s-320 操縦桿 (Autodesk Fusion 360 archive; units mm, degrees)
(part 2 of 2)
sketch "スケッチ34" plane through (0, -17.75, 0) normal (0, -1, 0) x axis (1, 0, 0)
  line L1 (26.4851, 42.5538) -> (46.528, 114.8261)
  line L2 (24.2607, 0.3616) -> (26.4851, 42.5538)
  line L3 (40.9088, -4.9758) -> (34.0399, -5.6547)
  line L4 (39.7489, 5.0904) -> (40.9088, 4.9758)
  line L5 (55.394, 34.5366) -> (39.7489, 5.0904)
  line L6 (75.4369, 106.8089) -> (55.394, 34.5366)
  line L7 (46.528, 114.8261) -> (75.4369, 106.8089)
  line L8 (69.2825, 103.327) -> (50.0099, 108.6717)
  line L9 (51.912, 40.691) -> (69.2825, 103.327)
  line L10 (32.6394, 46.0358) -> (51.912, 40.691)
  line L11 (50.0099, 108.6717) -> (32.6394, 46.0358)
  line L12 (26.4851, 42.5538) -> (55.394, 34.5366)
  line L13 (46.528, 114.8261) -> (26.4851, 42.5538)
  line L14 (30.25, 0) -> (60.9824, 110.8175)
  line L15 (30.8401, 5.9709) -> (40.9088, 4.9758)
  curve K1 (39.7489, 5.0904) -> (55.394, 34.5366)
  curve K2 (55.9608, 15.3561) -> (39.182, 24.2709)
  line L16 (56.7302, 39.3548) -> (47.2453, 33.4232)
  line L17 (34.0399, -5.6547) -> (28.0686, -16.8936)
  line L18 (19.6561, -9.6776) -> (19.6234, -9.6584)
  circle C1 centre (30.25, 0) radius 3.25
  circle C2 centre (40.417, 0) radius 2
  arc A1 centre (40.417, 0) radius 5 clockwise from (40.9088, 4.9758) to (40.9088, -4.9758)
  circle C3 centre (69.2825, 103.327) radius 2.75
  circle C4 centre (50.0099, 108.6717) radius 2.75
  circle C5 centre (32.6394, 46.0358) radius 2.75
  circle C6 centre (50.0099, 108.6717) radius 1.35
  circle C7 centre (69.2825, 103.327) radius 1.35
  circle C8 centre (32.6394, 46.0358) radius 1.35
  closed curve K3 centre (47.5714, 19.8135)
  arc A2 centre (8.7979, 1.4348) radius 15.5 clockwise from (24.2607, 0.3616) to (19.6234, -9.6584)
  arc A3 centre (23.0532, -14.2288) radius 5.6793 clockwise from (28.0686, -16.8936) to (19.6561, -9.6776)
  circle C9 centre (51.912, 40.691) radius 1.35
  circle C10 centre (51.912, 40.691) radius 2.75
  point P16 (50.0099, 108.6717)
  point P19 (50.0099, 108.6717)
  point P18 (32.6394, 46.0358)
  point P17 (69.2825, 103.327)
  point P11 (55.394, 34.5366)
  point P23 (55.394, 34.5366)
  point P5 (26.4851, 42.5538)
  point P24 (26.4851, 42.5538)
  point P13 (69.2825, 103.327)
  point P20 (69.2825, 103.327)
  point P15 (32.6394, 46.0358)
  point P22 (32.6394, 46.0358)
  point P34 (55.394, 34.5366)
  point P35 (39.7489, 5.0904)
  point P36 (39.182, 24.2709)
  point P37 (55.9608, 15.3561)
  point P27 (39.7489, 5.0904)
  point P38 (47.2453, 33.4232)
  point P39 (56.7302, 39.3548)
  point P21 (51.912, 40.691)
  point P46 (51.912, 40.691)
  point P14 (50.0099, 108.6717)
  equal C3 C4
  equal C4 C5
  concentric C4 C6
  concentric C3 C7
  concentric C5 C8
  equal C6 C7
  coincident P16 P19
  coincident P18 L10
  coincident P17 L9
  coincident P11 P23
  coincident P5 P24
  coincident P13 P20
  coincident P15 P22
  parallel L11 L13
  perpendicular L10 L11
  equal C6 C8
  coincident K3 P34
  coincident K3 P35
  coincident K3 P36
  coincident K3 P37
  parallel L5 K1
  coincident P23 K3
  coincident P23 P34
  coincident P27 P35
  coincident K3 P38
  coincident L6 P39
  tangent K3 L16
  coincident P21 P46
  concentric C9 C10
  equal C8 C9
  equal C5 C10
  dimension "d449" diameter C4 = 5.5
  dimension "d450" diameter C6 = 2.7
  dimension "d452" distance L7 L8 = 5
  dimension "d454" distance L6 L9 = 5
  dimension "d463" distance P14 L13 = 5
  dimension "d648" distance L10 L12 = 5
  dimension "d653" = 19
  dimension "d654" distance P23 P39 = 5
extrude "押し出し121" cut sketch "スケッチ34" profile of L5 L6 K3 L16 to an object
extrude "押し出し96" cut sketch "スケッチ34" profile of C3 C4 C5 C6 C7 C8 C9 C10 against normal blind 0.7
extrude "押し出し97" cut sketch "スケッチ34" profile of C6 C7 C8 C9 against normal blind 20
work_plane "作業平面6" AlongDistance 2
sketch "スケッチ35" plane through (-70, 0, 0) normal (-1, 0, 0) x axis (0, -1, 0)
  line L1 (11.625, 20.1351) -> (0, 0)
  line L2 (-11.625, 20.1351) -> (0, 0)
  line L3 (0, 23.25) -> (0, 0)
  circle C1 centre (0, 0) radius 23.25
  circle C2 centre (0, 0) radius 23.25
  point P1 (0, 0)
  point P2 (0, 0)
  point P4 (0, 0)
  point P6 (0, 0)
  point P5 (-11.625, 20.1351)
  point P3 (11.625, 20.1351)
  point P7 (0, 0)
  point P8 (0, 23.25)
  coincident P1 P2
  coincident P1 P4
  coincident P1 P6
  coincident P5 C1
  coincident P3 C1
  coincident P6 P7
  coincident C1 P8
  vertical L3
  symmetric L1 L2 L3
  equal C1 C2
  dimension "d472" angle L1 L2 = 60
extrude "押し出し99" cut sketch "スケッチ35" profile of L1 L2 C1 C2 along normal blind 6
sketch "スケッチ36" plane through (0, 0, 0) normal (0, 0, 1) x axis (1, 0, 0)
  line L1 (-70, 7.875) -> (-70, -7.875)
  line L2 (-97.5, 0) -> (0, 0)
  circle C1 centre (-73, 0) radius 3
  point P1 (0, 0)
  point P5 (0, 0)
  point P6 (-97.5, 0)
  point P7 (-97.5, 0)
  point P2 (-73, 0)
  tangent C1 L1
  coincident P1 P5
  horizontal L2
  coincident P6 P7
  coincident P2 L2
  dimension "d475" diameter C1 = 6
extrude "押し出し100" cut sketch "スケッチ36" profile of C1 no distance stored
work_plane "作業平面7" RotateAngle -30
sketch "スケッチ37" plane through (0, -7.875, 13.6399) normal (0, -0.5, 0.866) x axis (0, -0.866, -0.5)
  line L1 (0, -76) -> (0, -70)
  circle C1 centre (0, -73) radius 3
  point P3 (0, -76)
  point P4 (0, -70)
  point P2 (0, -73)
  coincident C1 P3
  coincident C1 P4
  coincident P2 L1
work_plane "作業平面8" RotateAngle 30
sketch "スケッチ38" plane through (0, 7.875, 13.6399) normal (0, 0.5, 0.866) x axis (0, -0.866, 0.5)
  line L1 (0, -70) -> (0, -76)
  circle C1 centre (0, -73) radius 3
  point P3 (0, -76)
  point P4 (0, -70)
  point P2 (0, -73)
  coincident C1 P3
  coincident C1 P4
  coincident P2 L1
extrude "押し出し101" cut sketch "スケッチ38" against normal blind 5
extrude "押し出し102" cut sketch "スケッチ37" against normal blind 5
work_plane "作業平面9" RotateAngle -90
extrude "押し出し103" new body sketch "スケッチ36" profile of C1 blind 13.5 from offset 10
sketch "スケッチ40" plane through (0, 0, 23.5) normal (0, 0, 1) x axis (-1, 0, 0)
  circle C1 centre (73, 0) radius 3
  circle C2 centre (73, 0) radius 4.5
  concentric C1 C2
  dimension "d489" diameter C2 = 9
extrude "押し出し104" add sketch "スケッチ40" along normal blind 1.5
sketch "スケッチ41" plane through (8, 0, 0) normal (1, 0, 0) x axis (0, 1, 0)
  line L1 (-19.1147, -8.074) -> (-32.7694, 24.2525)
  line L2 (14.5382, -14.5382) -> (14.9765, -14.9765)
  line L3 (1.3727, -15.6901) -> (14.5382, -14.5382)
  line L4 (-14.5382, 14.5382) -> (-15.6901, 1.3727)
  line L5 (-22.1855, 22.1855) -> (-14.5382, 14.5382)
  line L6 (3.2527, -35.7796) -> (-15.7847, -13.4687)
  line L7 (28.8089, -61.3359) -> (3.2527, -35.7796)
  line L8 (13.8593, -32.2441) -> (35.88, -54.2648)
  line L9 (18.1019, -20.9304) -> (13.8593, -25.173)
  line L10 (14.9765, -17.8049) -> (18.1019, -20.9304)
  arc A1 centre (-26.7817, 26.7817) radius 6.5 clockwise from (-32.7694, 24.2525) to (-22.1855, 22.1855)
  arc A2 centre (0, 0) radius 20.75 clockwise from (-15.7847, -13.4687) to (-19.1147, -8.074)
  arc A3 centre (0, 0) radius 15.75 clockwise from (1.3727, -15.6901) to (-15.6901, 1.3727)
  circle C1 centre (-26.7817, 26.7817) radius 2
  circle C2 centre (-26.7817, 26.7817) radius 2
  circle C3 centre (32.3445, -57.8003) radius 2
  arc A4 centre (32.3445, -57.8003) radius 5 clockwise from (35.88, -54.2648) to (28.8089, -61.3359)
  arc A5 centre (17.3948, -28.7085) radius 5 clockwise from (13.8593, -32.2441) to (13.8593, -25.173)
  arc A6 centre (16.3907, -16.3907) radius 2 clockwise from (14.9765, -17.8049) to (14.9765, -14.9765)
sketch "スケッチ42" plane through (0, 0, 0) normal (-1, 0, 0) x axis (0, -1, 0)
  line L1 (-8.0798, 13.5196) -> (23.4471, 32.3612)
  line L2 (32.3612, 23.4472) -> (13.5196, -8.0798)
  arc A1 centre (0, 0) radius 15.75 clockwise from (-8.0798, 13.5196) to (13.5196, -8.0798)
  arc A2 centre (26.7817, 26.7817) radius 6.5 clockwise from (23.4471, 32.3612) to (32.3612, 23.4472)
  circle C1 centre (26.7817, 26.7817) radius 3.25
  circle C2 centre (26.7817, 26.7817) radius 3.5
  concentric C1 C2
  dimension "d615" diameter C1 = 6.5
extrude "押し出し117" new body sketch "スケッチ42" profile of C1 along normal blind 1.6
extrude "押し出し118" add sketch "スケッチ5" profile of C1 to an object second side blind -12
sketch "スケッチ43" plane through (0, 20.8728, 0) normal (0, 1, 0) x axis (-1, 0, 0)
  line L1 (-27.6519, -1.5) -> (-32.8481, -1.5)
  arc A1 centre (-30.25, 0) radius 3 clockwise from (-32.8481, -1.5) to (-27.6519, -1.5)
component_from_bodies "ボディ -> コンポーネント33"
component_from_bodies "ボディ -> コンポーネント34"
component_from_bodies "ボディ -> コンポーネント35"
component_from_bodies "ボディ -> コンポーネント36"
component_from_bodies "ボディ -> コンポーネント37"
component_from_bodies "ボディ -> コンポーネント38"
component_from_bodies "ボディ -> コンポーネント39"
component_from_bodies "ボディ -> コンポーネント40"
component_from_bodies "ボディ -> コンポーネント41"
component_from_bodies "ボディ -> コンポーネント42"
component_from_bodies "ボディ -> コンポーネント43"
component_from_bodies "ボディ -> コンポーネント44"
component_from_bodies "ボディ -> コンポーネント45"
component_from_bodies "ボディ -> コンポーネント46"
component_from_bodies "ボディ -> コンポーネント47"
component_from_bodies "ボディ -> コンポーネント48"
component_from_bodies "ボディ -> コンポーネント49"
component_from_bodies "ボディ -> コンポーネント50"
component_from_bodies "ボディ -> コンポーネント51"
component_from_bodies "ボディ -> コンポーネント52"
component_from_bodies "ボディ -> コンポーネント53"
component_from_bodies "ボディ -> コンポーネント54"
component_from_bodies "ボディ -> コンポーネント55"
component_from_bodies "ボディ -> コンポーネント56"
component_from_bodies "ボディ -> コンポーネント57"
component_from_bodies "ボディ -> コンポーネント58"
component_from_bodies "ボディ -> コンポーネント59"
component_from_bodies "ボディ -> コンポーネント60"
component_from_bodies "ボディ -> コンポーネント61"
component_from_bodies "ボディ -> コンポーネント62"
component_from_bodies "ボディ -> コンポーネント63"
component_from_bodies "ボディ -> コンポーネント64"
component_from_bodies "ボディ -> コンポーネント65"
component_from_bodies "ボディ -> コンポーネント66"
component_from_bodies "ボディ -> コンポーネント67"
component_from_bodies "ボディ -> コンポーネント68"
component_from_bodies "ボディ -> コンポーネント69"
fillet "フィレット1" radius 2.5
fillet "フィレット1" radius 2.5
fillet "フィレット2" radius 2.5
work_plane "作業平面10"
base_feature "基準フィーチャ1"
position "位置8"
sketch "スケッチ54" plane through (0, 0, 0) normal (0, 1, 0) x axis (1, 0, 0)
copy_paste "コピーと貼り付け1"
base_feature "基準フィーチャ1"
position "位置11"
copy_paste "コピーと貼り付け4"
copy_paste "コピーと貼り付け5"
copy_paste "コピーと貼り付け6"
base_feature "基準フィーチャ1"
base_feature "基準フィーチャ1"
remove_instance "RemoveInstance1"
position "位置10"
base_feature "基準フィーチャ1"
base_feature "基準フィーチャ1"
remove_instance "RemoveInstance2"
position "位置12"
base_feature "基準フィーチャ1"
base_feature "基準フィーチャ1"
position "位置13"
remove_instance "RemoveInstance3"
base_feature "基準フィーチャ1"
position "位置14"
remove_instance "RemoveInstance4"
base_feature "基準フィーチャ1"
position "位置15"
sketch "スケッチ55" plane through (0, -15.75, 0) normal (0, 1, 0) x axis (-1, 0, 0)
  line L1 (-56.7302, 39.3548) -> (-74.7688, 104.3999)
  line L2 (-47.2453, 33.4232) -> (-56.7302, 39.3548)
  line L3 (-40.9088, 4.9758) -> (-39.7489, 5.0904)
  line L4 (-34.0399, -5.6547) -> (-40.9088, -4.9758)
  line L5 (-28.0686, -16.8936) -> (-34.0399, -5.6547)
  line L6 (-19.6234, -9.6584) -> (-19.6561, -9.6776)
  line L7 (-26.4851, 42.5538) -> (-24.2607, 0.3616)
  line L8 (-45.8599, 112.417) -> (-26.4851, 42.5538)
  line L9 (-73.0278, 107.477) -> (-48.937, 114.158)
  line L10 (-37.167, 0) -> (-45.417, 0)
  line L11 (-37.167, 0) -> (-39.7489, 5.0904)
  line L12 (-39.7489, -5.0904) -> (-37.167, 0)
  arc A1 centre (-72.3597, 105.0679) radius 2.5 clockwise from (-74.7688, 104.3999) to (-73.0278, 107.477)
  closed curve K1 centre (-47.5714, 19.8135)
  arc A2 centre (-40.417, 0) radius 5 clockwise from (-40.9088, -4.9758) to (-40.9088, 4.9758)
  arc A3 centre (-23.0532, -14.2288) radius 5.6793 clockwise from (-19.6561, -9.6776) to (-28.0686, -16.8936)
  arc A4 centre (-8.7979, 1.4348) radius 15.5 clockwise from (-19.6234, -9.6584) to (-24.2607, 0.3616)
  arc A5 centre (-48.2689, 111.7489) radius 2.5 clockwise from (-48.937, 114.158) to (-45.8599, 112.417)
  circle C1 centre (-69.2825, 103.327) radius 1.35
  circle C2 centre (-50.0099, 108.6717) radius 1.35
  circle C3 centre (-32.6394, 46.0358) radius 1.35
  circle C4 centre (-30.25, 0) radius 3.25
  circle C5 centre (-40.417, 0) radius 2
  circle C6 centre (-40.417, 0) radius 5
  circle C7 centre (-51.912, 40.691) radius 1.35
  point P28 (-37.167, 0)
  point P30 (-37.167, 0)
  point P29 (-45.417, 0)
  point P27 (-40.417, 0)
  point P7 (-39.7489, 5.0904)
  point P31 (-39.7489, 5.0904)
  point P32 (-37.167, 0)
  point P33 (-37.167, 0)
  point P34 (-39.7489, -5.0904)
  concentric A2 C6
  equal A2 C6
  horizontal L10
  coincident P28 P30
  coincident C6 P29
  coincident P27 L10
  coincident P7 P31
  coincident P28 P32
  coincident P28 P33
  coincident L4 P34
  symmetric L10 L11 L12
  dimension "d727" distance P27 P28 = 3.25
place_component sketch "スケッチ55"
extrude "押し出し1" new body sketch "スケッチ55" profile of L3 A2 L4 C5 C6 L11 L12 along normal blind 2.5
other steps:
base_feature "基準フィーチャ1" bodies "XH2"
base_feature "基準フィーチャ1"
base_feature "基準フィーチャ1"
base_feature "基準フィーチャ1"
base_feature "基準フィーチャ1"
base_feature "基準フィーチャ1"
base_feature "基準フィーチャ1"
base_feature "基準フィーチャ1"
base_feature "基準フィーチャ1"
base_feature "基準フィーチャ1" bodies "ESP32"
base_feature "基準フィーチャ1"
base_feature "基準フィーチャ1"
base_feature "基準フィーチャ1" bodies "LED"
base_feature "基準フィーチャ1"
base_feature "基準フィーチャ1"
base_feature "基準フィーチャ1" bodies "XH"
base_feature "基準フィーチャ1" bodies "XH3"
base_feature "基準フィーチャ1"
base_feature "基準フィーチャ1"
base_feature "基準フィーチャ1"
base_feature "基準フィーチャ1"
base_feature "基準フィーチャ1"
base_feature "基準フィーチャ1"
base_feature "基準フィーチャ1"
base_feature "基準フィーチャ1"
base_feature "基準フィーチャ1"
base_feature "基準フィーチャ1"
base_feature "基準フィーチャ1"
base_feature "基準フィーチャ1"
base_feature "基準フィーチャ1"
base_feature "基準フィーチャ1"
base_feature "基準フィーチャ1"
base_feature "基準フィーチャ1"
base_feature "基準フィーチャ1"
base_feature "基準フィーチャ1"
base_feature "基準フィーチャ1"
base_feature "基準フィーチャ1"
fillet "フィレット1" radius 2.5
create_component "CreateComponent33"
reparent_decal "デカールを再ペアレント化33"
remove_body "RemoveBody33"
create_component "CreateComponent34"
reparent_decal "デカールを再ペアレント化34"
remove_body "RemoveBody34"
create_component "CreateComponent35"
reparent_decal "デカールを再ペアレント化35"
remove_body "RemoveBody35"
create_component "CreateComponent36"
reparent_decal "デカールを再ペアレント化36"
remove_body "RemoveBody36"
create_component "CreateComponent37"
reparent_decal "デカールを再ペアレント化37"
remove_body "RemoveBody37"
create_component "CreateComponent38"
reparent_decal "デカールを再ペアレント化38"
remove_body "RemoveBody38"
create_component "CreateComponent39"
reparent_decal "デカールを再ペアレント化39"
remove_body "RemoveBody39"
create_component "CreateComponent40"
reparent_decal "デカールを再ペアレント化40"
remove_body "RemoveBody40"
create_component "CreateComponent41"
reparent_decal "デカールを再ペアレント化41"
remove_body "RemoveBody41"
create_component "CreateComponent42"
reparent_decal "デカールを再ペアレント化42"
remove_body "RemoveBody42"
create_component "CreateComponent43"
reparent_decal "デカールを再ペアレント化43"
remove_body "RemoveBody43"
create_component "CreateComponent44"
reparent_decal "デカールを再ペアレント化44"
remove_body "RemoveBody44"
create_component "CreateComponent45"
reparent_decal "デカールを再ペアレント化45"
remove_body "RemoveBody45"
create_component "CreateComponent46"
reparent_decal "デカールを再ペアレント化46"
remove_body "RemoveBody46"
create_component "CreateComponent47"
reparent_decal "デカールを再ペアレント化47"
remove_body "RemoveBody47"
create_component "CreateComponent48"
reparent_decal "デカールを再ペアレント化48"
remove_body "RemoveBody48"
create_component "CreateComponent49"
reparent_decal "デカールを再ペアレント化49"
remove_body "RemoveBody49"
create_component "CreateComponent50"
reparent_decal "デカールを再ペアレント化50"
remove_body "RemoveBody50"
create_component "CreateComponent51"
reparent_decal "デカールを再ペアレント化51"
remove_body "RemoveBody51"
create_component "CreateComponent52"
reparent_decal "デカールを再ペアレント化52"
remove_body "RemoveBody52"
create_component "CreateComponent53"
reparent_decal "デカールを再ペアレント化53"
remove_body "RemoveBody53"
create_component "CreateComponent54"
reparent_decal "デカールを再ペアレント化54"
remove_body "RemoveBody54"
create_component "CreateComponent55"
reparent_decal "デカールを再ペアレント化55"
remove_body "RemoveBody55"
create_component "CreateComponent56"
reparent_decal "デカールを再ペアレント化56"
remove_body "RemoveBody56"
create_component "CreateComponent57"
reparent_decal "デカールを再ペアレント化57"
remove_body "RemoveBody57"
create_component "CreateComponent58"
reparent_decal "デカールを再ペアレント化58"
remove_body "RemoveBody58"
create_component "CreateComponent59"
reparent_decal "デカールを再ペアレント化59"
remove_body "RemoveBody59"
create_component "CreateComponent60"
reparent_decal "デカールを再ペアレント化60"
remove_body "RemoveBody60"
create_component "CreateComponent61"
reparent_decal "デカールを再ペアレント化61"
remove_body "RemoveBody61"
create_component "CreateComponent62"
reparent_decal "デカールを再ペアレント化62"
remove_body "RemoveBody62"
create_component "CreateComponent63"
reparent_decal "デカールを再ペアレント化63"
remove_body "RemoveBody63"
create_component "CreateComponent64"
reparent_decal "デカールを再ペアレント化64"
remove_body "RemoveBody64"
create_component "CreateComponent65"
reparent_decal "デカールを再ペアレント化65"
remove_body "RemoveBody65"
create_component "CreateComponent66"
reparent_decal "デカールを再ペアレント化66"
remove_body "RemoveBody66"
create_component "CreateComponent67"
reparent_decal "デカールを再ペアレント化67"
remove_body "RemoveBody67"
create_component "CreateComponent68"
reparent_decal "デカールを再ペアレント化68"
remove_body "RemoveBody68"
create_component "CreateComponent69"
reparent_decal "デカールを再ペアレント化69"
remove_body "RemoveBody69"
create_component "CreateComponent70"
create_component "CreateComponent71"
create_component "CreateComponent72"
create_component "CreateComponent1"
create_component "CreateComponent2"
create_component "CreateComponent73"
create_component "CreateComponent1"
create_component "CreateComponent2"
create_component "CreateComponent74"
create_component "CreateComponent1"
create_component "CreateComponent2"
create_component "CreateComponent75"
create_component "CreateComponent1"
create_component "CreateComponent77"
create_component "CreateComponent78" sketch "スケッチ55"
named bodies: "ESP32", "XH", "XH2", "XH3", "LED"

design "基板取付用2連ボリューム B10kΩ"
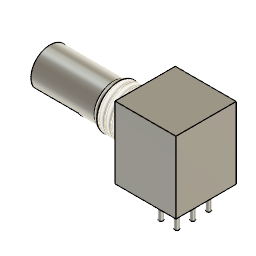
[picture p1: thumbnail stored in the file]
sketch "スケッチ1" plane through (0, 0, 0) normal (0, 0, 1) x axis (1, 0, 0)
  line L1 (9.6, 0) -> (0, 0)
  line L2 (9.6, 9.5) -> (9.6, 0)
  line L3 (0, 9.5) -> (9.6, 9.5)
  line L4 (0, 0) -> (0, 9.5)
  point P1 (0, 0)
  point P2 (0, 0)
  point P5 (0, 9.5)
  point P4 (9.6, 9.5)
  horizontal L1
  vertical L2
  horizontal L3
  vertical L4
  coincident P1 P2
  dimension "d1" distance P2 P5 = 9.5
  dimension "d2" distance P4 P5 = 9.6
extrude "押し出し1" new body sketch "スケッチ1" along normal blind 11.3
sketch "スケッチ2" plane through (0, 0, 0) normal (-1, 0, 0) x axis (0, -1, 0)
  line L1 (0, 0) -> (-9.5, 0)
  line L2 (0, 11.3) -> (0, 0)
  line L3 (-9.5, 11.3) -> (0, 11.3)
  line L4 (-9.5, 0) -> (-9.5, 11.3)
  line L5 (-4.75, 0) -> (-4.75, 11.3)
  circle C1 centre (-4.75, 6.1) radius 3.5
  point P7 (-4.75, 11.3)
  point P8 (-4.75, 0)
  point P6 (-4.75, 6.1)
  midpoint L3 P7
  midpoint L1 P8
  coincident P6 L5
  dimension "d5" diameter C1 = 7
  dimension "d6" distance L1 P6 = 6.1
extrude "押し出し2" add sketch "スケッチ2" profile of C1 along normal blind 5
thread "ねじ" ThreadOffset 0 ThreadLength 10
sketch "スケッチ3" plane through (-5, 0, 0) normal (-1, 0, 0) x axis (0, -1, 0)
  circle C1 centre (-4.75, 6.1) radius 3.442
  circle C2 centre (-4.75, 6.1) radius 3
  concentric C1 C2
  dimension "d11" diameter C2 = 6
extrude "押し出し3" add sketch "スケッチ3" profile of C2 along normal blind 3
sketch "スケッチ4" plane through (-8, 0, 0) normal (-1, 0, 0) x axis (0, -1, 0)
  line L1 (-7, 4.6) -> (-7.3481, 4.6)
  line L2 (-2.1519, 4.6) -> (-7, 4.6)
  circle C1 centre (-4.75, 6.1) radius 3
  point P3 (-7.3481, 4.6)
  point P5 (-2.1519, 4.6)
  point P2 (-4.75, 6.1)
  coincident C1 P3
  horizontal L1
  parallel L1 L2
  coincident C1 P5
  dimension "d14" distance P2 L2 = 1.5
extrude "押し出し4" add sketch "スケッチ4" along normal blind 7
fillet "フィレット" radius 1
sketch "スケッチ5" plane through (0, 0, 0) normal (0, 0, -1) x axis (1, 0, 0)
  line L1 (0, -9.5) -> (0, 0)
  line L2 (9.6, -9.5) -> (0, -9.5)
  line L3 (9.6, 0) -> (9.6, -9.5)
  line L4 (0, 0) -> (9.6, 0)
  line L5 (5, 0) -> (5, -9.5)
  line L6 (5, -2.25) -> (5, -7.25)
  line L7 (6.25, 0) -> (6.25, -9.5)
  line L8 (7.5, 0) -> (7.5, -9.5)
  line L9 (5, -4.75) -> (7.5, -4.75)
  circle C1 centre (7.5, -7.25) radius 0.3466
  circle C2 centre (7.5, -4.75) radius 0.3466
  circle C3 centre (7.5, -2.25) radius 0.3466
  circle C4 centre (5, -7.25) radius 0.3466
  circle C5 centre (5, -4.75) radius 0.3466
  circle C6 centre (5, -2.25) radius 0.3466
  point P12 (5, -9.5)
  point P13 (5, 0)
  point P10 (5, -4.75)
  point P9 (5, -7.25)
  point P14 (5, -7.25)
  point P11 (5, -2.25)
  point P15 (5, -2.25)
  point P16 (6.25, -9.5)
  point P17 (6.25, 0)
  point P18 (7.5, -9.5)
  point P19 (7.5, 0)
  point P20 (7.5, -4.75)
  point P21 (5, -4.75)
  equal C1 C4
  equal C4 C5
  equal C5 C6
  equal C3 C6
  equal C2 C3
  coincident L2 P12
  coincident L4 P13
  perpendicular L4 L5
  midpoint P10 L5
  coincident P9 P14
  coincident P11 P15
  parallel L5 L6
  midpoint P10 L6
  coincident L2 P16
  coincident L4 P17
  perpendicular L4 L7
  coincident L2 P18
  coincident L4 P19
  perpendicular L4 L8
  midpoint L8 P20
  coincident P10 P21
  midpoint L7 L9
  symmetric C3 C6 L7
  symmetric C2 C5 L7
  symmetric C1 C4 L7
  dimension "d19" distance P9 P11 = 5
  dimension "d21" distance P20 P21 = 2.5
  dimension "d22" distance L1 P10 = 5
extrude "押し出し5" add sketch "スケッチ5" profile of C1 C2 C3 C4 C5 C6 along normal blind 3.5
